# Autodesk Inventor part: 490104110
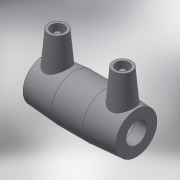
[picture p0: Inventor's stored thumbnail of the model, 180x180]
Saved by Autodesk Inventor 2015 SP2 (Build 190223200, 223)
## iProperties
Created: 2017-06
Part Number: 490104110
Material: Generic
Description: PLASSON COUPLER 110-110
Document SubType Name: Modeling
Designer: KIM
Mass: 55.0731 g
Surface Area: 148.067 cm^2
Volume: 55.0731 cm^3
Density: 1 g/cm^3
Appearance: Default
Author: KIM
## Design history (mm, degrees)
derived "490104.ipt"
feature "Solid1::490104.ipt"
tag "TaggingFeature1"
body "Solid1"
other parameters: "d0" = 163, "d2" = 135, "d4" = 54.33333, "d5" = 121.5, "d6" = 104.5, "d8" = 168 deg, "d10" = 32, "d11" = 10.66667, "d13" = 163, "d14" = 17.6296, "d17" = 104.5, "d19" = 3.52592, "d20" = 168 deg, "d22" = 126.9, "d23" = 135, "d24" = 123.093, "d25" = 135 deg, "d26" = 65.2, "d27" = 135 deg, "d29" = 81, "d30" = 14, "d31" = 57.05, "d34" = 5 deg, "d35" = 15, "d39" = 5 deg, "d41" = 4, "d42" = 14, "d43" = 0, "d45" = 4, "d46" = 14, "d47" = 0, "d48" = 3, "d49" = 0, "d50" = 3, "d51" = 0, "d52" = 23.2, "d53" = 5.8, "L_" = 163, "D_" = 135, "A_" = 81, "d_2" = 12
